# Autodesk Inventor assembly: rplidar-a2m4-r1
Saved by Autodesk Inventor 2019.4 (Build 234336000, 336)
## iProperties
Created: 2020-05
Part Number: rplidar-a2m4-r1
Document SubType Name: Assembly
Designer: Administrator
Title: rplidar-a2m4-r1
Author: Administrator
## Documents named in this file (2)
- c:\worker\convert-fusion-r04\tmp\job-1\3\output\files\88492291-068e-4573-82a5-cdd8cfb136cd\rplidar-a2m4-r1.iam
- c:\worker\convert-fusion-r04\tmp\job-1\3\output\files\88492291-068e-4573-82a5-cdd8cfb136cd\RPLIDAR A2.iam
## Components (1 placed, 1 different names)
1. RPLIDAR A2:1 [sub-assembly]
